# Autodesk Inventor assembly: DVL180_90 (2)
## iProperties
Created: 2009-09
Part Number: DVL180_90 (2)
Document SubType Name: Assembly
Designer: TB
Mass: 11224.5 g
Surface Area: 9437.3 cm^2
Volume: 11224.5 cm^3
Density: 1 g/cm^3
Description: KM DVL 180/90 - 100 mm
Slaglengde: 100.000 mm
Author: TB
